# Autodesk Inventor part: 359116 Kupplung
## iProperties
Company: Mayer & Müller AG Schaltgeräte
Created: 2006-10
Part Number: 359116 Kupplung
Material: 1.0718.07
Description: Scheibe
Document SubType Name: Modeling
Designer: Natti_01
Density: 7.84 g/cm^3
HalbzeugNorm: DIN 671
Zweck: 266464
Abmessung: Rd. 35
Author: Natti_01
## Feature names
1. Extrusion3
2. Bohrung1 [Hole]
3. Bohrung2 [Hole]
4. Extrusion4
5. Bohrung3 [Hole]
